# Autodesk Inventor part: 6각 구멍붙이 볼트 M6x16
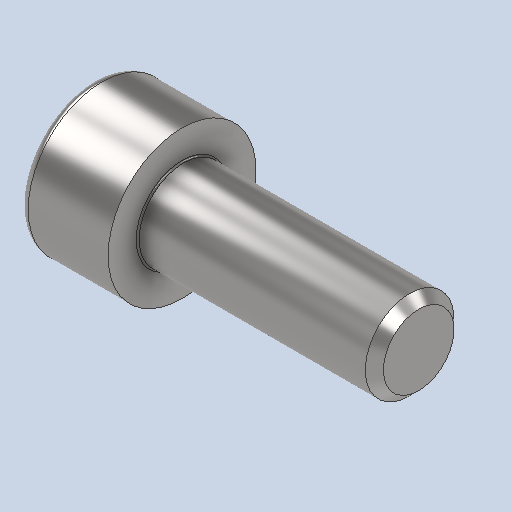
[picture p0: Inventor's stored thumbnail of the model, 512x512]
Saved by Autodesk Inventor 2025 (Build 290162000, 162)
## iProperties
Created: 2026-08
Part Number: 6각 구멍붙이 볼트 M6x16
Material: 강철, 연강
Description: 6각머리 태핑 나사
Document SubType Name: Modeling
Designer: KDI
Density: 7.85 g/cm^3
Appearance: 기본값
Author: jhkim
Sending System: Autodesk Inventor 2027
Preprocessor: ST-DEVELOPER v20.1
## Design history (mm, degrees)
feature "Solid1"
node "솔리드1"
